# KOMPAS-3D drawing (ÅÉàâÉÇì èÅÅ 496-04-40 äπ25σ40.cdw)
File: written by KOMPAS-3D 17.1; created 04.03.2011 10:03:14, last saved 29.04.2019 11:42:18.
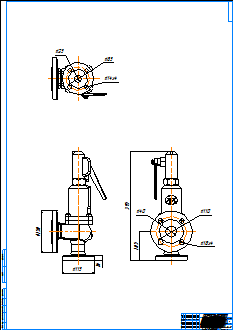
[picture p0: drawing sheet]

Sheet 1: A0, portrait

Title block, sheet 1: name: Прегран Ду 25х40; material: Внимание! Данный продукт является объектом авторского права ООО «Торговый Дом АДЛ». / Запрещается изменение, копирование, распространение / (в том числе путем копирования на другие сайты и ресурсы в Интернете) / или любое иное использование информации и объектов без предварительного / согласия правообладателя (ООО «Торговый Дом АДЛ»).; scale: 1:1; sheets: 1; organisation: ООО "Торговый дом АДЛ"; sheet format: A0; stored path: C:\Users\tra\Desktop\2д чертежи\Предохранительные клапаны ПРЕГРАН\ПРЕГРАН 496\ПРЕГРАН КПП 496-04-40\KOMPAS 2D\Прегран Ду 25х40.cdw

Views: Спереди 1, Проекционный вид 2, Проекционный вид 3
Dimensions and other numbers on the sheet: 105; 115; 150; 110; 18; 16; 40; 85; 25; 14; 395; 1:1; 1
